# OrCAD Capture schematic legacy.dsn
size A; title: CIP Demo; rev: A; note: PCA000000001
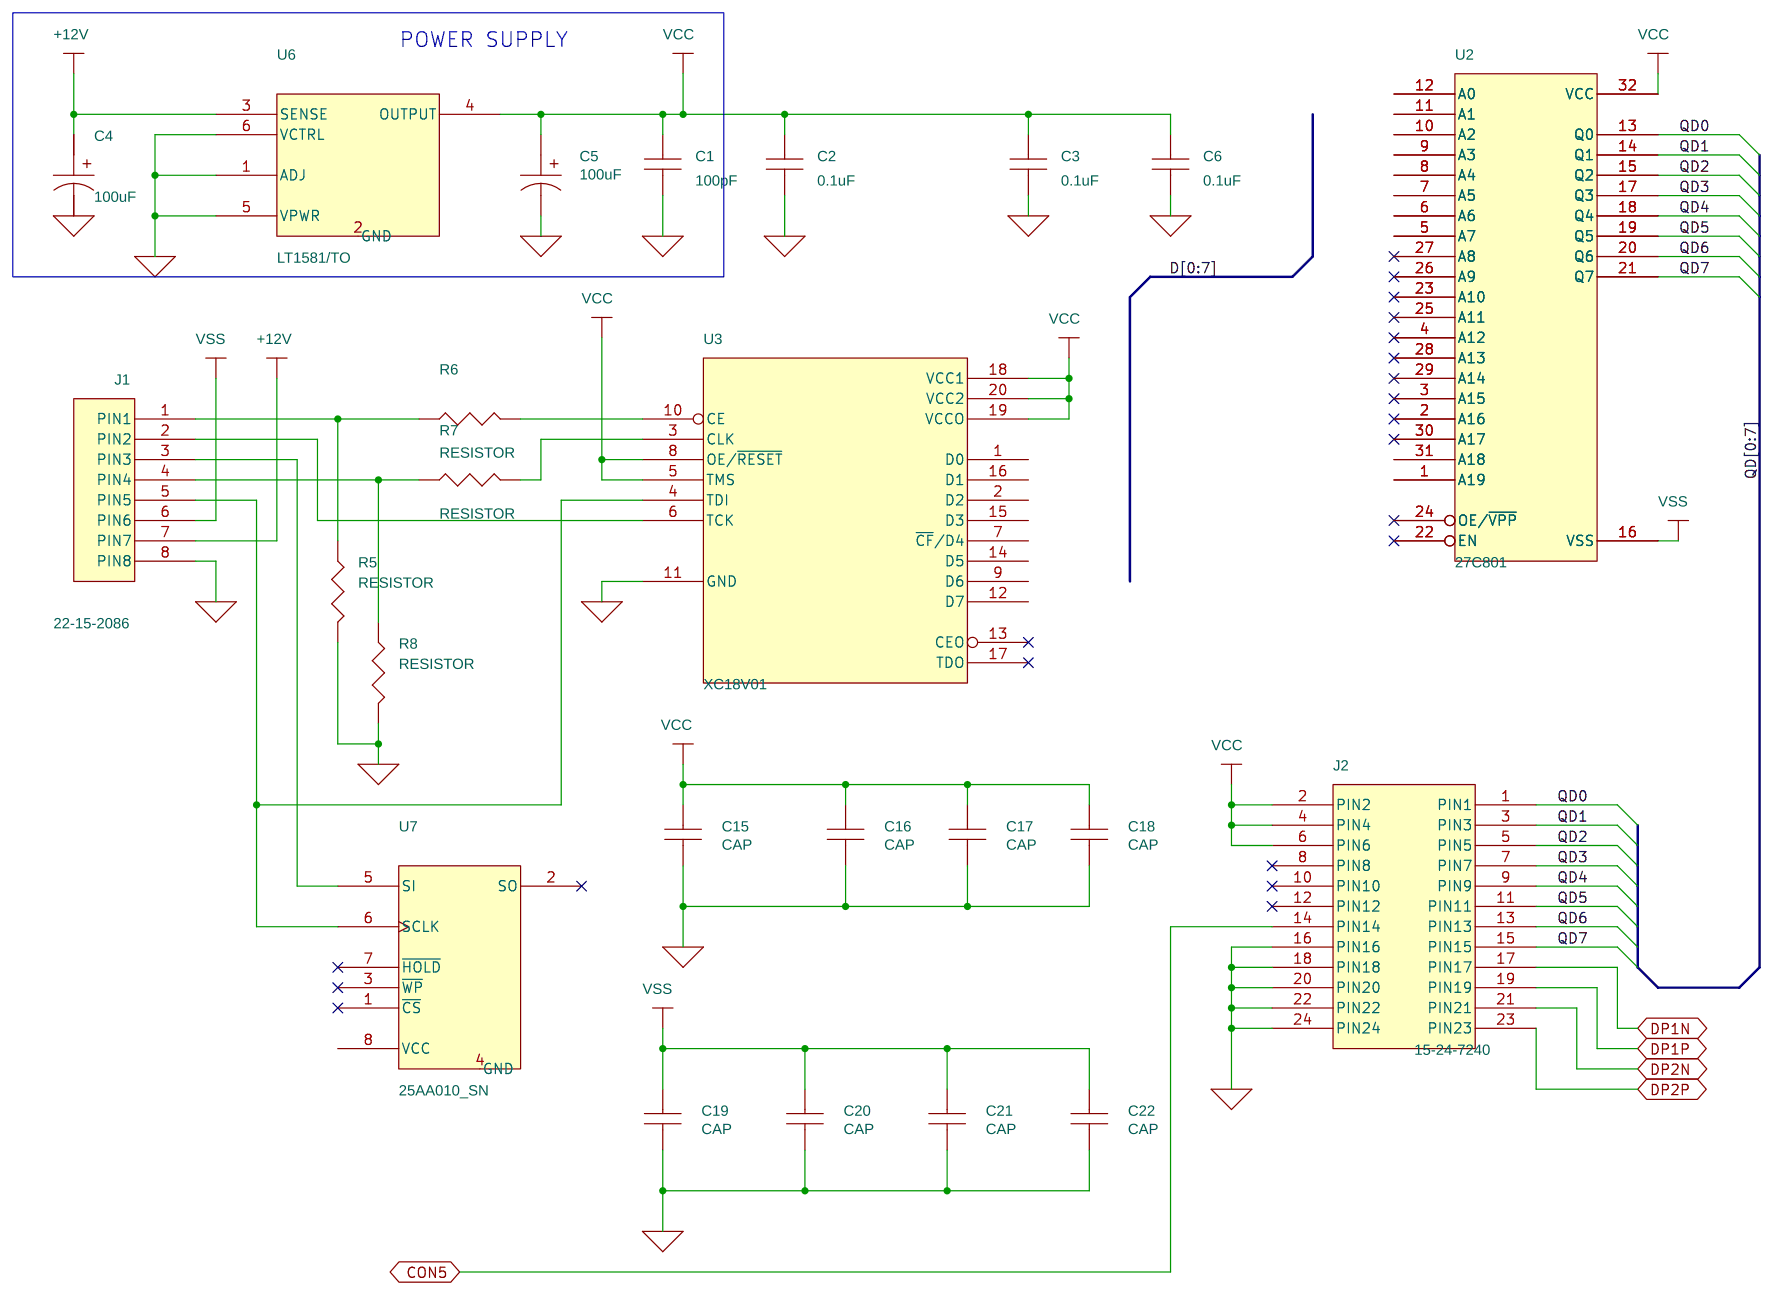
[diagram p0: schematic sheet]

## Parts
C1  100pF  [CAPC1608X86N]
C2  0.1uF  [CAPC1608X86N]
C3  0.1uF  [CAPC1608X86N]
C4  100uF  [CAPMP6032X280N]
C5  100uF  [CAPMP6032X280N]
C6  0.1uF  [CAPC1608X86N]
C15  CAP
C16  CAP
C17  CAP
C18  CAP
C19  CAP
C20  CAP
C21  CAP
C22  CAP
J1  22-15-2086  [MOLEX_4455A-8]
J2  15-24-7240  [MOLEX_42385-24]
R5  RESISTOR
R6  RESISTOR
R7  RESISTOR
R8  RESISTOR
U2  27C801  [PLCC127P1244X1498X357-32N]
U3  XC18V01  [SOIC127P1034X267-20N]
U6  LT1581/TO
U7  25AA010_SN

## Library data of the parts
C1 = CAP: CAP, Ceramic, SMD, 100 pF, 10 %, 50 V, 0603; CLASS: DISCRETE; Dielectric Type: Ceramic; Manufacturer: AVX; Manufacturer PN: 06035A101KAT2A; PART_NUMBER: EMA-00000491V22; PSpiceTemplate: C^@REFDES %1 %2 C^@REFDES 100pF \n.model C^@REFDES CAP C=1 DEV=0.1; Package Size: 0603; Rated Voltage: 50 V; Temperature Coefficient: C0G; Tolerance: 10%
C2 C3 C6 = CAP: CAP, Ceramic, SMD, 0.1 uF, 5.0 %, 16 V, 0603; CLASS: DISCRETE; Dielectric Type: Ceramic; Manufacturer: AVX; Manufacturer PN: 0603YC104JAT2A; PART_NUMBER: EMA-00000401; PSpiceTemplate: C^@REFDES %1 %2 C^@REFDES 0.1uF \n.model C^@REFDES CAP C=1 DEV=0.05; Package Size: 0603; Rated Voltage: 16 V; Temperature Coefficient: X7R; Tolerance: 5.0%
C4 C5 = CAP_P: CAP, Tantalum, SMD, 100 uF, 10 %, 6.3 V, 6032-28; CLASS: DISCRETE; Dielectric Type: Tantalum; HEIGHT: 2.80 mm; Manufacturer: AVX; Manufacturer PN: TPSC107K006R0150; Operating Temperature Maximum: 125 C; Operating Temperature Minimum: -55 C; PART_NUMBER: EMA-00000517; PSpiceTemplate: C^@REFDES %1 %2 C^@REFDES 100uF \n.model C^@REFDES CAP C=1 DEV=0.1; Package Height: 2.80 mm; Package Size: 6032-28; Part Number: EMA-00007000; ROOM: POWER SUPPLY; Rated Voltage: 6.3 V; Tolerance: 10%
C15-C22 = CAP
J1 = CONN_PCB_1X8_F: CONN, Header, 22-15-2086, 8, TH; CLASS: IO; Contact Voltage: 250 V; Manufacturer: Molex Inc; Operating Temperature Maximum: 75 C; Operating Temperature Minimum: 0.0 C; PART_NUMBER: EMA-00006006; Package Size: 20.22 x 7.9 x 7.7 mm
J2 = HDR_2X12_F: CONN, Header, 15-24-7240, 24, TH; CLASS: IO; Contact Voltage: 600 V; Manufacturer: Molex Inc; Operating Temperature Maximum: 105 C; Operating Temperature Minimum: -40 C; PART_NUMBER: EMA-00005995; Package Size: 51.6 x 9.6 x 11.34 mm
R5-R8 = RESISTOR
U2 = M27_CW_801_FBK: IC, Memory Devices, EEPROM, 27C801, PLCC-32; CLASS: IC; HEIGHT: 3.57 mm; Manufacturer: STMicroelectronics; Manufacturer PN: M27C801-100K1; Operating Temperature Maximum: 70 C; Operating Temperature Minimum: 0.0 C; PART_NUMBER: EMA-00007180V22; Package Height: 3.57 mm; Package Size: PLCC-32; Supply Voltage: 5.0 V
U3 = XC18VXXXSO20: IC, Memory Devices, PROM, XC18V01, SOIC-20; CLASS: IC; COMMENT: Test1234; HEIGHT: 1.67 mm; Manufacturer: Xilinx; Manufacturer PN: XC18V01SOG20C; Operating Temperature Maximum: 85 C; Operating Temperature Minimum: -40 C; PART_NUMBER: EMA-00007402; Package Height: 2.67 mm; Package Size: SOIC-20; Supply Voltage: 3.6 V
U6 = LT1581_TO
U7 = 25AA010_SN

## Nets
+12V: C4.1 J1.7(PIN7) U6.3(SENSE)
GND: U6.2(GND) U7.4(GND)
GND_SIGNAL: C1.2 C2.2 C3.2 C4.2 C5.2 C6.2 C15.2 C16.2 C17.2 C18.2 C19.2 C20.2 C21.2 C22.2 J1.8(PIN8) J2.16(PIN16) J2.18(PIN18) J2.20(PIN20) J2.22(PIN22) J2.24(PIN24) R5.2 R8.2 U3.11(GND) U6.1(ADJ) U6.5(VPWR) U6.6(VCTRL)
VCC: C1.1 C2.1 C3.1 C5.1 C6.1 C15.1 C16.1 C17.1 C18.1 J2.2(PIN2) J2.4(PIN4) J2.6(PIN6) U2.32(VCC) U3.5(TMS) U3.8(OE/~{RESET}) U3.18(VCC1) U3.19(VCCO) U3.20(VCC2) U6.4(OUTPUT) U7.8(VCC)
VSS: C19.1 C20.1 C21.1 C22.1 J1.6(PIN6) U2.16(VSS)
CON5: J2.14(PIN14)
DP1N: J2.17(PIN17)
DP1P: J2.19(PIN19)
DP2N: J2.21(PIN21)
DP2P: J2.23(PIN23)
QD0: J2.1(PIN1) U2.13(Q0)
QD1: J2.3(PIN3) U2.14(Q1)
QD2: J2.5(PIN5) U2.15(Q2)
QD3: J2.7(PIN7) U2.17(Q3)
QD4: J2.9(PIN9) U2.18(Q4)
QD5: J2.11(PIN11) U2.19(Q5)
QD6: J2.13(PIN13) U2.20(Q6)
QD7: J2.15(PIN15) U2.21(Q7)
N00614: J1.1(PIN1) R5.1 R6.1
N02756: R7.2 U3.3(CLK)
N02853: J1.2(PIN2) U3.6(TCK)
N06434: J1.3(PIN3) U7.5(SI)
N11467: J1.5(PIN5) U3.4(TDI) U7.6(SCLK)
N137874: J1.4(PIN4) R7.1 R8.1
N210142: R6.2 U3.10(CE)

Not connected (* = marked no-connect by the designer): J2 8(PIN8)* 10(PIN10)* 12(PIN12)*; U2 1(A19) 2(A16)* 3(A15)* 4(A12)* 5(A7) 6(A6) 7(A5) 8(A4) 9(A3) 10(A2) 11(A1) 12(A0) 22(EN)* 23(A10)* 24(OE/~{VPP})* 25(A11)* 26(A9)* 27(A8)* 28(A13)* 29(A14)* 30(A17)* 31(A18); U3 1(D0) 2(D2) 7(~{CF}/D4) 9(D6) 12(D7) 13(CEO)* 14(D5) 15(D3) 16(D1) 17(TDO)*; U7 1(~{CS})* 2(SO)* 3(~{WP})* 7(~{HOLD})*

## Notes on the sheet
- POWER SUPPLY
